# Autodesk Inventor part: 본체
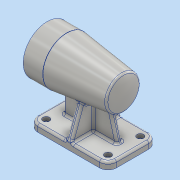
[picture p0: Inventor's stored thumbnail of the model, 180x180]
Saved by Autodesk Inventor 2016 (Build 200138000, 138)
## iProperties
Created: 2018-09
Part Number: 본체
Material: 알루미늄 6061
Document SubType Name: Modeling
Designer: 605-11
Density: 2.7 g/cm^3
Appearance: 알루미늄 - 평지
Mass: 736.858 g
Surface Area: 667.309 cm^2
Volume: 272.91 cm^3
Author: 605-11
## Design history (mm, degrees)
sketch "스케치1"
  geometry: 1 further point
sketch "스케치2"
  geometry: L1 (56, -35)-(-56, -35); L2 (-56, -35)-(-56, 35); L3 (-56, 35)-(56, 35); L4 (56, 35)-(56, -35); L5 (56, -35)-(-56, 35); L6 (-56, -35)-(56, 35); 1 further point
  constraints: 12 end point, 2 midpoint, 2 parallel, 1 horizontal, 1 perpendicular
  dimensions: "d0" = 112 distance of L1.start L1.end; "d1" = 70 distance of L1.end L2.end
extrude "돌출1" new body sketch "스케치2" distance "d2" = 10; taper "d3" = 0 deg
fillet "모깎기1" dims "d4" = 12
sketch "스케치3"
  geometry: L1 (56, -23)-(56, 23) reference; L2 (44, 35)-(-44, 35) reference; L3 (-56, 23)-(-56, -23) reference; L4 (-44, -35)-(44, -35) reference; A1 r 12 centre (44, -23) between (44, -35) and (56, -23) reference; A2 r 12 centre (-44, 23) between (-44, 35) and (-56, 23) reference; A3 r 12 centre (-44, -23) between (-56, -23) and (-44, -35) reference; A4 r 12 centre (44, 23) between (56, 23) and (44, 35) reference; 5 further points
  constraints: 4 coincident
hole "구멍1" sketch "스케치3" at (44, -23), (44, 23), (-44, 23), (-44, -23) diameter "d5" = 5.5; stored, may be unused: countersink angle "d9" = 90 deg, drill point angle "d11" = 118 deg; dims "d6" = 6, "d7" = 9.5, "d8" = 5.4, "d10" = 8
sketch "스케치5"
  geometry: L1 (-18.771, 81.764)-(-38, 10); L2 (38, 81.764)-(38, 10); L3 (56, 10)-(56, 0) reference; L4 (-56, 0)-(-56, 10) reference; L5 (44, 10)-(-44, 10) reference; L6 (-38, 10)-(38, 10); L7 (39.25, 10)-(48.75, 10) reference; L8 (38, 81.764)-(-18.771, 81.764); 1 further point
  constraints: 8 end point, 2 point on line, 1 collinear, 1 horizontal, 1 vertical
  dimensions: "d12" = 18 distance between parallel lines of L3 L2; "d13" = 18 distance from line of L1.end L4; "d16" = 105 deg angle of L1 L5; "d17" = 56.77093 distance of L2.start L1.start
extrude "돌출2" join sketch "스케치5" stored distance "d18" = 8; taper "d19" = 0 deg
sketch "스케치6"
  geometry: L1 (0, -35)-(10, -35) reference; L2 (10, 35)-(0, 35) reference; L3 (10, -35)-(77.066, -10.59); L4 (77.066, -10.59)-(77.066, 10.59); L5 (77.066, 10.59)-(10, 35); L6 (10, -35)-(10, 35); 1 further point
  constraints: 8 end point, 2 vertical
  dimensions: "d21" = 20 deg angle of L3 L1; "d22" = 20 deg angle of L5 L2
extrude "돌출3" join sketch "스케치6" stored distance "d23" = 8; taper "d24" = 0 deg
sketch "스케치7"
  geometry: L1 (-49.61, 74)-(77.985, 74); L2 (65.731, 108)-(37.731, 108); L3 (37.731, 108)-(-42.539, 98.144); L4 (-46.269, 74)-(65.731, 74); L5 (65.731, 108)-(65.731, 74); A1 r 80 centre (33.731, 74) between (-42.539, 98.144) and (-46.269, 74); 1 further point
  constraints: 10 end point, 3 point on line, 2 horizontal, 2 point on circle, 1 centre point, 1 collinear, 1 perpendicular
  dimensions: "d25" = 74 distance from line of L1 point (0, 0); "d26" = 68 diameter of L2 L1; "d27" = 28 distance of L2.start L2.end; "d31" = 80 radius of A1; "d32" = 112 horizontal distance of L2.start L4.start; "d33" = 7 deg angle of L3 L2
revolve "회전1" sketch "스케치7" stored, may be unused: angle "d55" = 90 deg
sketch "스케치8"
  geometry: L1 (-71.135, 74)-(104.549, 74); L2 (65.731, 40)-(65.731, 108) reference; L3 (65.731, 74)-(50.731, 74); L4 (50.731, 74)-(50.731, 95); L5 (50.731, 95)-(65.731, 95); L6 (65.731, 95)-(65.731, 74); L7 (50.731, 74)-(-3.269, 74); L8 (-3.269, 74)-(-3.269, 98); L9 (-3.269, 98)-(50.731, 98); L10 (50.731, 98)-(50.731, 74); L11 (-3.269, 74)-(-15.269, 74); L12 (-15.269, 74)-(-15.269, 95); L13 (-15.269, 95)-(-3.269, 95); L14 (-3.269, 95)-(-3.269, 74); L15 (-15.269, 74)-(-33.269, 74); L16 (-33.269, 74)-(-33.269, 91.5); L17 (-33.269, 91.5)-(-15.269, 91.5); L18 (-15.269, 91.5)-(-15.269, 74); L19 (-33.269, 74)-(-37.269, 74); L20 (-37.269, 74)-(-37.269, 90); L21 (-37.269, 90)-(-33.269, 90); L22 (-33.269, 90)-(-33.269, 74); L23 (-37.269, 74)-(-40.269, 74); L24 (-40.269, 74)-(-40.269, 84.5); L25 (-40.269, 84.5)-(-37.269, 84.5); L26 (-37.269, 84.5)-(-37.269, 74); 1 further point
  constraints: 50 end point, 12 parallel, 7 horizontal, 6 perpendicular, 1 midpoint, 1 point on line
  dimensions: "d56" = 74 distance from line of L1 point (0, 0); "d57" = 15 distance of L4.end L5.end; "d58" = 54 distance of L8.end L9.end; "d59" = 12 distance of L12.end L13.end; "d60" = 18 distance of L16.end L17.end; "d61" = 4 distance of L20.end L21.end; "d62" = 3 distance of L24.end L25.end; "d63" = 42 diameter of L5 L1; "d64" = 48 diameter of L9 L1; "d65" = 35 diameter of L17 L1; "d66" = 32 diameter of L21 L1; "d67" = 21 diameter of L25 L1
revolve "회전2" sketch "스케치8" stored, may be unused: angle "d68" = 90 deg
sketch "스케치9"
  geometry: C1 r 34 at (0, 0) reference; 2 further points
  constraints: 1 vertical alignment
  dimensions: "d69" = 26 distance of point (0, 26) C1.centre
hole "구멍2" sketch "스케치9" at (0, 26) diameter "d70" = 3.242; stored, may be unused: countersink angle "d74" = 90 deg, drill point angle "d76" = 118 deg; dims "d71" = 8, "d72" = 19.05, "d73" = 4.775, "d75" = 11
sketch "스케치10"
  geometry: L1 (100, 0)-(100, 10) reference; 2 further points
  constraints: 1 other
  dimensions: "d80" = 56 distance from line of point (44, 3) L1; "d81" = 3 vertical distance of L1.start point (44, 3)
fillet "모깎기2" dims "d82" = 3
fillet "모깎기3" dims "d83" = 0.3, "d84" = 3
fillet "모깎기4" dims "d85" = 3
fillet "모깎기5" dims "d86" = 3
fillet "모깎기6" dims "d87" = 3
chamfer "모따기1" distance "d88" = 1; stored, may be unused: second distance "d89" = 2, angle "d90" = 45 deg
feature "엠보싱1" dims "d0" = 112, "d1" = 70, "d92" = 0.5, "d93" = 0
fillet "모깎기8" dims "d94" = 3
fillet "모깎기9" dims "d95" = 3
fillet "모깎기10" dims "d96" = 3
node "솔리드1"
pattern_circular "원형 패턴1" dims angle "d78" = 360 deg
node "투영된 루프1"
